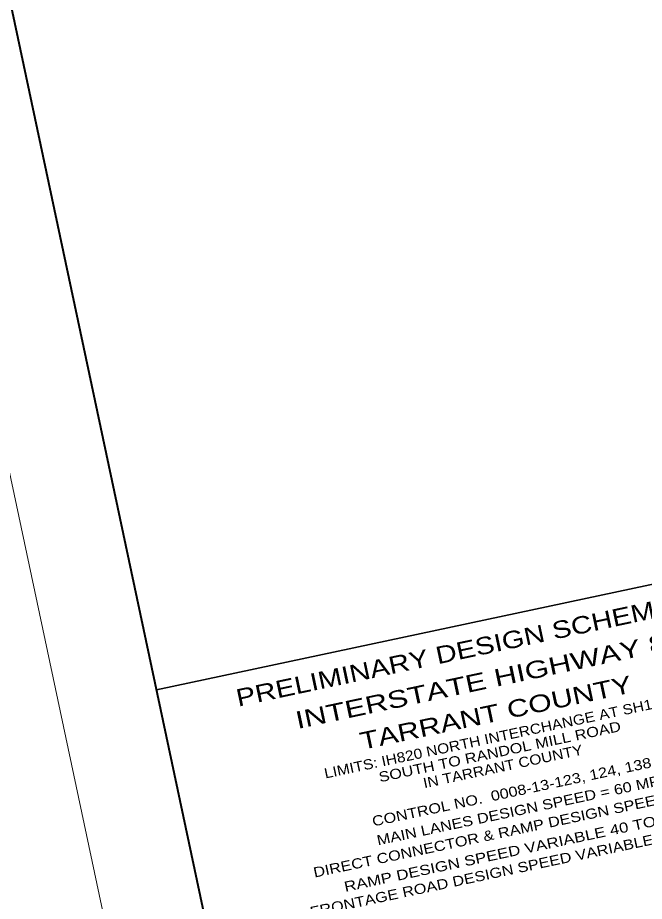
# Model space of a CAD drawing. Extents: x 2357218 to 2371708, y 6973728 to 6980157.
# Drawn here: x 2357852 to 2358486, y 6974296 to 6975190 of the extents above; entities that cross this region are included whole.
import ezdxf
from ezdxf.enums import TextEntityAlignment as Align

# ---------------------------------------------------------------- set-up
doc = ezdxf.new("R2010")
doc.units = 0
doc.header["$LTSCALE"] = 2
for name, color, linetype, lineweight in [('44', 7, 'Continuous', 13), ('62', 7, 'Continuous', 13), ('63', 7, 'Continuous', 13)]:
    doc.layers.add(name, color=color, linetype=linetype, lineweight=lineweight)
doc.layers.add('61', color=7, linetype='Continuous')

msp = doc.modelspace()

# ---------------------------------------------------------------- linework, layer by layer
at = {"layer": '44'}
msp.add_line((2358039.664, 6973807.926), (2357291.149, 6977329.415), dxfattribs=at)
at = {"layer": '44', "lineweight": 40}
msp.add_lwpolyline([(2358116.692, 6973926.537), (2357409.76, 6977252.388), (2370517.53, 6980038.532)], dxfattribs=at)
at = {"layer": '62', "lineweight": 35}
msp.add_line((2357992.598, 6974510.353), (2358629.393, 6974645.709), dxfattribs=at)
at = {"layer": '63', "lineweight": 35}
msp.add_line((2357992.598, 6974510.353), (2358629.393, 6974645.709), dxfattribs=at)

# ---------------------------------------------------------------- texts
at = {"layer": '61'}
for s, width, p in [('LIMITS: IH820 NORTH INTERCHANGE AT SH121', 1.15, (2358337.676, 6974457.599)), ('SOUTH TO RANDOL MILL ROAD', 1.2, (2358340.837, 6974442.73)), ('IN TARRANT COUNTY', 1.15, (2358343.998, 6974427.863))]:
    msp.add_text(s, height=10.2, rotation=12, dxfattribs=dict(at, width=width)).set_placement(p, align=Align.CENTER)
at = {"layer": '62'}
for s, height, width, p in [('PRELIMINARY DESIGN SCHEMATIC', 17.5, 1.25, (2358075.107, 6974493.187)), ('INTERSTATE HIGHWAY 820', 17.5, 1.35, (2358135.192, 6974470.647)), ('TARRANT COUNTY', 17.5, 1.3, (2358200.336, 6974449.473)), ('CONTROL NO.  0008-13-123, 124, 138', 10.2, 1.2, (2358211.832, 6974372.018))]:
    msp.add_text(s, height=height, rotation=12, dxfattribs=dict(at, width=width)).set_placement(p)
for s, width, p in [('MAIN LANES DESIGN SPEED = 60 MPH', 1.2, (2358365.357, 6974384.543)), ('DIRECT CONNECTOR & RAMP DESIGN SPEED = 50 MPH', 1.2, (2358369.219, 6974366.37)), ('RAMP DESIGN SPEED VARIABLE 40 TO 50 MPH', 1.25, (2358373.497, 6974346.243)), ('FRONTAGE ROAD DESIGN SPEED VARIABLE 35 TO 40 MPH', 1.2, (2358378.055, 6974329.019))]:
    msp.add_text(s, height=10.2, rotation=12, dxfattribs=dict(at, width=width)).set_placement(p, align=Align.CENTER)
at = {"layer": '63', "width": 1.2}
for s, p in [('MAIN LANES DESIGN SPEED = 60 MPH', (2358365.357, 6974384.543)), ('DIRECT CONNECTOR & RAMP DESIGN SPEED = 50 MPH', (2358369.219, 6974366.37))]:
    msp.add_text(s, height=10.2, rotation=12, dxfattribs=at).set_placement(p, align=Align.CENTER)

doc.saveas('drawing.dxf')
